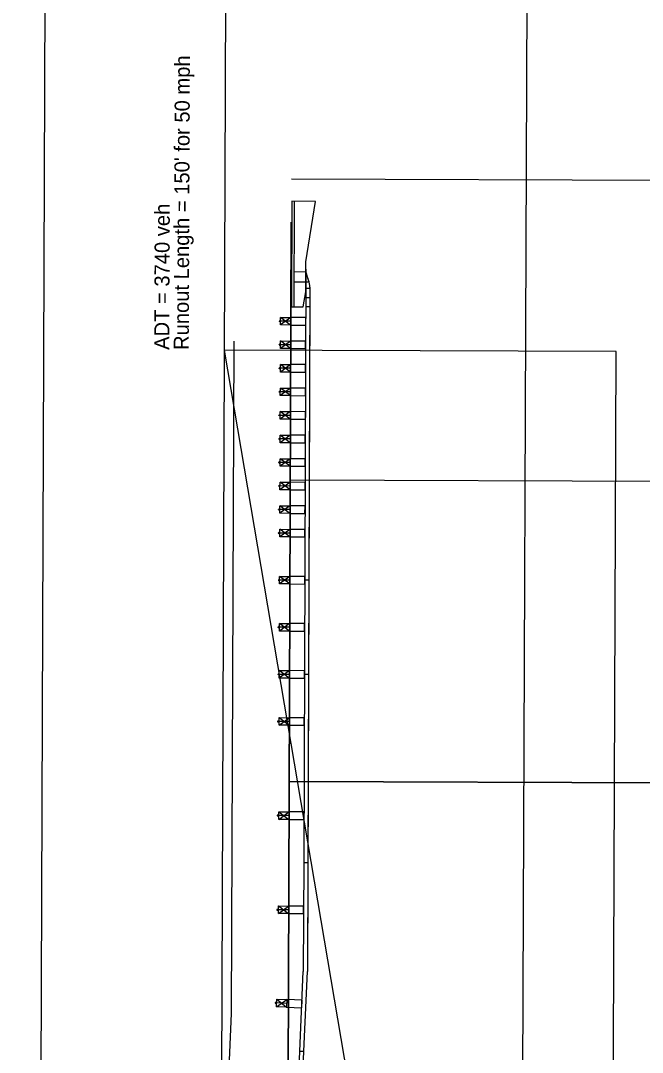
# Model space of a CAD drawing. Extents: x 15359458 to 15360238, y 8797399 to 8799222.
# Drawn here: x 15359893 to 15359934.3, y 8798014.5 to 8798083 of the extents above; entities that cross this region are included whole.
import ezdxf

# ---------------------------------------------------------------- set-up
doc = ezdxf.new("R2010")
doc.units = 0
for name, color, linetype in [('_CIVIL_CONSTRUCTION', 7, 'Continuous'), ('Alignment', 7, 'Continuous'), ('CorridorGraphics', 7, 'Continuous'), ('MeshTop', 7, 'Continuous'), ('PhoTerrainTriangle', 7, 'Continuous'), ('PhoTerrainVoid', 7, 'Continuous')]:
    doc.layers.add(name, color=color, linetype=linetype)

msp = doc.modelspace()

# ---------------------------------------------------------------- linework, layer by layer
at = {"layer": '_CIVIL_CONSTRUCTION'}
for p, q in [((15359911.001, 8798071.023), (15359910.975, 8798064.023)), ((15359912.584, 8798071.017), (15359911.001, 8798071.023)), ((15359911.168, 8798071.022), (15359911.141, 8798064.022)), ((15359911.944, 8798067.018), (15359912.584, 8798071.013)), ((15359912.584, 8798071.013), (15359912.584, 8798071.017)), ((15359911.937, 8798065.019), (15359911.944, 8798067.018)), ((15359911.15, 8798066.356), (15359911.968, 8798066.352)), ((15359911.942, 8798066.519), (15359911.793, 8798027.124)), ((15359911.942, 8798066.519), (15359911.968, 8798066.519)), ((15359911.967, 8798066.269), (15359911.968, 8798066.519)), ((15359911.148, 8798065.689), (15359912.15, 8798065.685)), ((15359912.117, 8798065.785), (15359912.062, 8798065.928)), ((15359911.766, 8798064.02), (15359911.937, 8798065.019)), ((15359912.208, 8798065.227), (15359911.937, 8798065.228)), ((15359912.209, 8798065.323), (15359912.064, 8798027.123)), ((15359912.208, 8798065.227), (15359912.111, 8798039.623)), ((15359910.975, 8798064.023), (15359911.766, 8798064.02)), ((15359912.204, 8798064.018), (15359911.933, 8798064.019)), ((15359912.206, 8798064.622), (15359911.935, 8798064.623)), ((15359910.262, 8798062.817), (15359910.264, 8798063.317)), ((15359910.931, 8798063.315), (15359910.262, 8798062.817)), ((15359910.929, 8798062.815), (15359910.264, 8798063.317)), ((15359910.931, 8798063.314), (15359910.929, 8798062.815)), ((15359911.93, 8798063.311), (15359910.931, 8798063.314)), ((15359911.928, 8798062.811), (15359911.93, 8798063.311)), ((15359910.209, 8798063.077), (15359910.18, 8798063.078)), ((15359910.18, 8798063.058), (15359910.18, 8798063.078)), ((15359910.209, 8798063.057), (15359910.18, 8798063.058)), ((15359910.247, 8798063.107), (15359910.209, 8798063.107)), ((15359910.209, 8798063.027), (15359910.209, 8798063.107)), ((15359910.247, 8798063.091), (15359910.209, 8798063.091)), ((15359910.246, 8798063.043), (15359910.209, 8798063.043)), ((15359910.246, 8798063.027), (15359910.209, 8798063.027)), ((15359910.246, 8798062.987), (15359910.247, 8798063.147)), ((15359910.263, 8798062.987), (15359910.246, 8798062.987)), ((15359910.263, 8798063.147), (15359910.247, 8798063.147)), ((15359910.93, 8798063.065), (15359910.263, 8798063.067)), ((15359910.929, 8798062.815), (15359911.928, 8798062.811)), ((15359910.203, 8798061.515), (15359910.174, 8798061.515)), ((15359910.174, 8798061.495), (15359910.174, 8798061.515)), ((15359910.203, 8798061.495), (15359910.174, 8798061.495)), ((15359910.241, 8798061.545), (15359910.203, 8798061.545)), ((15359910.203, 8798061.465), (15359910.203, 8798061.545)), ((15359910.241, 8798061.529), (15359910.203, 8798061.529)), ((15359910.241, 8798061.481), (15359910.203, 8798061.481)), ((15359910.24, 8798061.465), (15359910.203, 8798061.465)), ((15359910.24, 8798061.425), (15359910.241, 8798061.585)), ((15359910.257, 8798061.425), (15359910.24, 8798061.425)), ((15359910.257, 8798061.585), (15359910.241, 8798061.585)), ((15359910.256, 8798061.255), (15359910.258, 8798061.755)), ((15359910.925, 8798061.752), (15359910.256, 8798061.255)), ((15359910.924, 8798061.502), (15359910.257, 8798061.505)), ((15359910.923, 8798061.252), (15359910.258, 8798061.755)), ((15359910.925, 8798061.752), (15359910.923, 8798061.252)), ((15359910.923, 8798061.252), (15359911.922, 8798061.248)), ((15359911.924, 8798061.748), (15359910.925, 8798061.752)), ((15359911.922, 8798061.248), (15359911.924, 8798061.748)), ((15359910.197, 8798059.952), (15359910.168, 8798059.953)), ((15359910.168, 8798059.933), (15359910.168, 8798059.953)), ((15359910.197, 8798059.932), (15359910.168, 8798059.933)), ((15359910.235, 8798059.982), (15359910.197, 8798059.982)), ((15359910.197, 8798059.902), (15359910.197, 8798059.982)), ((15359910.235, 8798059.966), (15359910.197, 8798059.966)), ((15359910.235, 8798059.918), (15359910.197, 8798059.918)), ((15359910.235, 8798059.902), (15359910.197, 8798059.902)), ((15359910.234, 8798059.862), (15359910.235, 8798060.022)), ((15359910.251, 8798059.862), (15359910.234, 8798059.862)), ((15359910.252, 8798060.022), (15359910.235, 8798060.022)), ((15359910.25, 8798059.692), (15359910.252, 8798060.192)), ((15359910.919, 8798060.19), (15359910.25, 8798059.692)), ((15359910.918, 8798059.94), (15359910.251, 8798059.942)), ((15359910.917, 8798059.69), (15359910.252, 8798060.192)), ((15359910.919, 8798060.189), (15359910.917, 8798059.69)), ((15359911.918, 8798060.186), (15359910.919, 8798060.189)), ((15359911.916, 8798059.686), (15359911.918, 8798060.186)), ((15359910.917, 8798059.69), (15359911.916, 8798059.686)), ((15359910.244, 8798058.13), (15359910.246, 8798058.63)), ((15359910.913, 8798058.627), (15359910.244, 8798058.13)), ((15359910.911, 8798058.127), (15359910.246, 8798058.63)), ((15359910.913, 8798058.627), (15359910.911, 8798058.127)), ((15359911.912, 8798058.623), (15359910.913, 8798058.627)), ((15359911.91, 8798058.123), (15359911.912, 8798058.623)), ((15359910.191, 8798058.39), (15359910.162, 8798058.39)), ((15359910.162, 8798058.37), (15359910.162, 8798058.39)), ((15359910.191, 8798058.37), (15359910.162, 8798058.37)), ((15359910.191, 8798058.34), (15359910.192, 8798058.42)), ((15359910.229, 8798058.404), (15359910.191, 8798058.404)), ((15359910.229, 8798058.356), (15359910.191, 8798058.356)), ((15359910.229, 8798058.34), (15359910.191, 8798058.34)), ((15359910.229, 8798058.42), (15359910.192, 8798058.42)), ((15359910.228, 8798058.3), (15359910.229, 8798058.46)), ((15359910.245, 8798058.3), (15359910.228, 8798058.3)), ((15359910.246, 8798058.46), (15359910.229, 8798058.46)), ((15359910.912, 8798058.377), (15359910.245, 8798058.38)), ((15359910.911, 8798058.127), (15359911.91, 8798058.123)), ((15359910.186, 8798056.827), (15359910.156, 8798056.828)), ((15359910.156, 8798056.808), (15359910.156, 8798056.828)), ((15359910.185, 8798056.807), (15359910.156, 8798056.808)), ((15359910.185, 8798056.777), (15359910.186, 8798056.857)), ((15359910.223, 8798056.793), (15359910.185, 8798056.793)), ((15359910.223, 8798056.777), (15359910.185, 8798056.777)), ((15359910.223, 8798056.857), (15359910.186, 8798056.857)), ((15359910.223, 8798056.841), (15359910.186, 8798056.841)), ((15359910.24, 8798056.897), (15359910.223, 8798056.897)), ((15359910.223, 8798056.737), (15359910.223, 8798056.897)), ((15359910.239, 8798056.737), (15359910.223, 8798056.737)), ((15359910.238, 8798056.567), (15359910.24, 8798057.067)), ((15359910.907, 8798057.065), (15359910.238, 8798056.567)), ((15359910.906, 8798056.815), (15359910.239, 8798056.817)), ((15359910.905, 8798056.565), (15359910.24, 8798057.067)), ((15359910.907, 8798057.064), (15359910.905, 8798056.565)), ((15359910.905, 8798056.565), (15359911.905, 8798056.561)), ((15359911.906, 8798057.061), (15359910.907, 8798057.064)), ((15359911.905, 8798056.561), (15359911.906, 8798057.061)), ((15359910.18, 8798055.265), (15359910.15, 8798055.265)), ((15359910.15, 8798055.245), (15359910.15, 8798055.265)), ((15359910.18, 8798055.245), (15359910.15, 8798055.245)), ((15359910.179, 8798055.215), (15359910.18, 8798055.295)), ((15359910.217, 8798055.231), (15359910.179, 8798055.231)), ((15359910.217, 8798055.215), (15359910.179, 8798055.215)), ((15359910.217, 8798055.295), (15359910.18, 8798055.295)), ((15359910.217, 8798055.279), (15359910.18, 8798055.279)), ((15359910.234, 8798055.335), (15359910.217, 8798055.335)), ((15359910.217, 8798055.175), (15359910.217, 8798055.335)), ((15359910.233, 8798055.175), (15359910.217, 8798055.175)), ((15359910.233, 8798055.005), (15359910.234, 8798055.505)), ((15359910.901, 8798055.502), (15359910.233, 8798055.005)), ((15359910.899, 8798055.002), (15359910.234, 8798055.505)), ((15359910.9, 8798055.252), (15359910.234, 8798055.255)), ((15359910.901, 8798055.502), (15359910.899, 8798055.002)), ((15359911.901, 8798055.498), (15359910.901, 8798055.502)), ((15359911.899, 8798054.998), (15359911.901, 8798055.498)), ((15359910.899, 8798055.002), (15359911.899, 8798054.998)), ((15359910.174, 8798053.702), (15359910.144, 8798053.703)), ((15359910.144, 8798053.683), (15359910.144, 8798053.703)), ((15359910.174, 8798053.682), (15359910.144, 8798053.683)), ((15359910.211, 8798053.732), (15359910.174, 8798053.732)), ((15359910.174, 8798053.652), (15359910.174, 8798053.732)), ((15359910.211, 8798053.716), (15359910.174, 8798053.716)), ((15359910.228, 8798053.772), (15359910.211, 8798053.772)), ((15359910.211, 8798053.612), (15359910.211, 8798053.772)), ((15359910.227, 8798053.442), (15359910.229, 8798053.942)), ((15359910.895, 8798053.94), (15359910.227, 8798053.442)), ((15359910.894, 8798053.69), (15359910.228, 8798053.692)), ((15359910.893, 8798053.44), (15359910.229, 8798053.942)), ((15359910.895, 8798053.94), (15359910.893, 8798053.44)), ((15359911.895, 8798053.936), (15359910.895, 8798053.94)), ((15359911.893, 8798053.436), (15359911.895, 8798053.936)), ((15359910.211, 8798053.668), (15359910.174, 8798053.668)), ((15359910.211, 8798053.652), (15359910.174, 8798053.652)), ((15359910.227, 8798053.612), (15359910.211, 8798053.612)), ((15359910.893, 8798053.44), (15359911.893, 8798053.436)), ((15359910.221, 8798051.88), (15359910.223, 8798052.38)), ((15359910.889, 8798052.377), (15359910.221, 8798051.88)), ((15359910.887, 8798051.877), (15359910.223, 8798052.38)), ((15359910.889, 8798052.377), (15359910.887, 8798051.877)), ((15359910.889, 8798052.377), (15359910.887, 8798051.877)), ((15359911.889, 8798052.373), (15359910.889, 8798052.377)), ((15359911.889, 8798052.373), (15359910.889, 8798052.377)), ((15359911.887, 8798051.873), (15359911.889, 8798052.373)), ((15359911.887, 8798051.873), (15359911.889, 8798052.373)), ((15359910.168, 8798052.14), (15359910.138, 8798052.14)), ((15359910.138, 8798052.12), (15359910.138, 8798052.14)), ((15359910.168, 8798052.12), (15359910.138, 8798052.12)), ((15359910.205, 8798052.17), (15359910.168, 8798052.17)), ((15359910.168, 8798052.09), (15359910.168, 8798052.17)), ((15359910.205, 8798052.154), (15359910.168, 8798052.154)), ((15359910.205, 8798052.106), (15359910.168, 8798052.106)), ((15359910.205, 8798052.09), (15359910.168, 8798052.09)), ((15359910.222, 8798052.21), (15359910.205, 8798052.21)), ((15359910.205, 8798052.05), (15359910.205, 8798052.21)), ((15359910.221, 8798052.05), (15359910.205, 8798052.05)), ((15359910.888, 8798052.127), (15359910.222, 8798052.13)), ((15359910.887, 8798051.877), (15359911.887, 8798051.873)), ((15359910.887, 8798051.877), (15359911.887, 8798051.873)), ((15359910.162, 8798050.578), (15359910.132, 8798050.578)), ((15359910.132, 8798050.558), (15359910.132, 8798050.578)), ((15359910.162, 8798050.558), (15359910.132, 8798050.558)), ((15359910.199, 8798050.607), (15359910.162, 8798050.608)), ((15359910.162, 8798050.528), (15359910.162, 8798050.608)), ((15359910.199, 8798050.591), (15359910.162, 8798050.592)), ((15359910.199, 8798050.543), (15359910.162, 8798050.544)), ((15359910.199, 8798050.527), (15359910.162, 8798050.528)), ((15359910.199, 8798050.487), (15359910.2, 8798050.647)), ((15359910.216, 8798050.487), (15359910.199, 8798050.487)), ((15359910.216, 8798050.647), (15359910.2, 8798050.647)), ((15359910.215, 8798050.317), (15359910.217, 8798050.817)), ((15359910.883, 8798050.815), (15359910.215, 8798050.317)), ((15359910.882, 8798050.565), (15359910.216, 8798050.567)), ((15359910.881, 8798050.315), (15359910.217, 8798050.817)), ((15359910.883, 8798050.815), (15359910.881, 8798050.315)), ((15359910.881, 8798050.315), (15359911.881, 8798050.311)), ((15359911.883, 8798050.811), (15359910.883, 8798050.815)), ((15359911.881, 8798050.311), (15359911.883, 8798050.811)), ((15359910.126, 8798048.995), (15359910.127, 8798049.015)), ((15359910.156, 8798048.995), (15359910.126, 8798048.995)), ((15359910.156, 8798049.015), (15359910.127, 8798049.015)), ((15359910.194, 8798049.045), (15359910.156, 8798049.045)), ((15359910.156, 8798048.965), (15359910.156, 8798049.045)), ((15359910.193, 8798049.029), (15359910.156, 8798049.029)), ((15359910.193, 8798048.981), (15359910.156, 8798048.981)), ((15359910.193, 8798048.965), (15359910.156, 8798048.965)), ((15359910.193, 8798048.925), (15359910.194, 8798049.085)), ((15359910.21, 8798048.925), (15359910.193, 8798048.925)), ((15359910.21, 8798049.085), (15359910.194, 8798049.085)), ((15359910.209, 8798048.755), (15359910.211, 8798049.255)), ((15359910.877, 8798049.252), (15359910.209, 8798048.755)), ((15359910.877, 8798049.002), (15359910.21, 8798049.005)), ((15359910.876, 8798048.752), (15359910.211, 8798049.255)), ((15359910.877, 8798049.252), (15359910.876, 8798048.752)), ((15359911.877, 8798049.248), (15359910.877, 8798049.252)), ((15359911.875, 8798048.749), (15359911.877, 8798049.248)), ((15359910.876, 8798048.752), (15359911.875, 8798048.749)), ((15359910.144, 8798045.89), (15359910.115, 8798045.89)), ((15359910.115, 8798045.87), (15359910.115, 8798045.89)), ((15359910.144, 8798045.87), (15359910.115, 8798045.87)), ((15359910.182, 8798045.92), (15359910.144, 8798045.92)), ((15359910.144, 8798045.84), (15359910.144, 8798045.92)), ((15359910.182, 8798045.904), (15359910.144, 8798045.904)), ((15359910.181, 8798045.856), (15359910.144, 8798045.856)), ((15359910.181, 8798045.84), (15359910.144, 8798045.84)), ((15359910.181, 8798045.8), (15359910.182, 8798045.96)), ((15359910.198, 8798045.8), (15359910.181, 8798045.8)), ((15359910.198, 8798045.96), (15359910.182, 8798045.96)), ((15359910.197, 8798045.63), (15359910.199, 8798046.13)), ((15359910.866, 8798046.127), (15359910.197, 8798045.63)), ((15359910.865, 8798045.877), (15359910.198, 8798045.88)), ((15359910.864, 8798045.627), (15359910.199, 8798046.13)), ((15359910.866, 8798046.127), (15359910.864, 8798045.627)), ((15359910.864, 8798045.627), (15359911.863, 8798045.624)), ((15359911.865, 8798046.123), (15359910.866, 8798046.127)), ((15359911.863, 8798045.624), (15359911.865, 8798046.123)), ((15359912.135, 8798045.873), (15359911.864, 8798045.874)), ((15359910.132, 8798042.765), (15359910.103, 8798042.765)), ((15359910.103, 8798042.745), (15359910.103, 8798042.765)), ((15359910.132, 8798042.745), (15359910.103, 8798042.745)), ((15359910.17, 8798042.795), (15359910.132, 8798042.795)), ((15359910.132, 8798042.715), (15359910.132, 8798042.795)), ((15359910.17, 8798042.779), (15359910.132, 8798042.779)), ((15359910.17, 8798042.731), (15359910.132, 8798042.731)), ((15359910.169, 8798042.675), (15359910.17, 8798042.835)), ((15359910.187, 8798042.835), (15359910.17, 8798042.835)), ((15359910.185, 8798042.505), (15359910.187, 8798043.005)), ((15359910.854, 8798043.002), (15359910.185, 8798042.505)), ((15359910.853, 8798042.752), (15359910.186, 8798042.755)), ((15359910.852, 8798042.502), (15359910.187, 8798043.005)), ((15359910.854, 8798043.002), (15359910.852, 8798042.502)), ((15359911.853, 8798042.998), (15359910.854, 8798043.002)), ((15359911.851, 8798042.499), (15359911.853, 8798042.998)), ((15359910.17, 8798042.715), (15359910.132, 8798042.715)), ((15359910.186, 8798042.675), (15359910.169, 8798042.675)), ((15359910.852, 8798042.502), (15359911.851, 8798042.499)), ((15359910.121, 8798039.64), (15359910.091, 8798039.64)), ((15359910.091, 8798039.62), (15359910.091, 8798039.64)), ((15359910.12, 8798039.62), (15359910.091, 8798039.62)), ((15359910.12, 8798039.59), (15359910.121, 8798039.67)), ((15359910.158, 8798039.606), (15359910.12, 8798039.606)), ((15359910.158, 8798039.59), (15359910.12, 8798039.59)), ((15359910.158, 8798039.67), (15359910.121, 8798039.67)), ((15359910.158, 8798039.654), (15359910.121, 8798039.654)), ((15359910.175, 8798039.71), (15359910.158, 8798039.71)), ((15359910.158, 8798039.55), (15359910.158, 8798039.71)), ((15359910.174, 8798039.55), (15359910.158, 8798039.55)), ((15359910.174, 8798039.38), (15359910.175, 8798039.88)), ((15359910.842, 8798039.877), (15359910.174, 8798039.38)), ((15359910.841, 8798039.627), (15359910.174, 8798039.63)), ((15359910.84, 8798039.377), (15359910.175, 8798039.88)), ((15359910.842, 8798039.877), (15359910.84, 8798039.377)), ((15359910.84, 8798039.377), (15359911.84, 8798039.374)), ((15359911.842, 8798039.873), (15359910.842, 8798039.877)), ((15359911.84, 8798039.374), (15359911.842, 8798039.873)), ((15359912.111, 8798039.623), (15359911.841, 8798039.624)), ((15359910.16, 8798036.255), (15359910.829, 8798036.752)), ((15359910.162, 8798036.755), (15359910.827, 8798036.252)), ((15359910.829, 8798036.752), (15359910.827, 8798036.252)), ((15359911.83, 8798036.749), (15359910.829, 8798036.752)), ((15359911.828, 8798036.248), (15359911.83, 8798036.749)), ((15359910.064, 8798036.505), (15359910.057, 8798036.505)), ((15359910.828, 8798036.502), (15359910.161, 8798036.505)), ((15359910.827, 8798036.252), (15359911.828, 8798036.248)), ((15359910.137, 8798030.005), (15359910.805, 8798030.502)), ((15359910.139, 8798030.505), (15359910.803, 8798030.002)), ((15359910.805, 8798030.502), (15359910.803, 8798030.002)), ((15359911.806, 8798030.499), (15359910.805, 8798030.502)), ((15359911.804, 8798029.998), (15359911.806, 8798030.499)), ((15359910.04, 8798030.255), (15359910.033, 8798030.255)), ((15359910.804, 8798030.252), (15359910.138, 8798030.255)), ((15359910.803, 8798030.002), (15359911.804, 8798029.998)), ((15359911.793, 8798027.124), (15359911.766, 8798019.9)), ((15359912.064, 8798027.123), (15359911.793, 8798027.124)), ((15359912.064, 8798027.123), (15359911.793, 8798027.124)), ((15359912.064, 8798027.123), (15359912.037, 8798019.897)), ((15359910.113, 8798023.755), (15359910.782, 8798024.252)), ((15359910.115, 8798024.255), (15359910.78, 8798023.752)), ((15359910.782, 8798024.252), (15359910.78, 8798023.752)), ((15359911.782, 8798024.249), (15359910.782, 8798024.252)), ((15359911.781, 8798023.748), (15359911.782, 8798024.249)), ((15359910.017, 8798024.005), (15359910.01, 8798024.005)), ((15359910.781, 8798024.002), (15359910.114, 8798024.005)), ((15359910.78, 8798023.752), (15359911.781, 8798023.748)), ((15359911.535, 8798014.625), (15359911.766, 8798019.9)), ((15359911.805, 8798014.613), (15359912.037, 8798019.897)), ((15359909.909, 8798017.826), (15359909.902, 8798017.827)), ((15359909.995, 8798017.572), (15359910.683, 8798018.043)), ((15359910.672, 8798017.793), (15359910.006, 8798017.822)), ((15359910.017, 8798018.072), (15359910.661, 8798017.543)), ((15359910.683, 8798018.043), (15359910.661, 8798017.543)), ((15359910.661, 8798017.543), (15359911.661, 8798017.499)), ((15359911.683, 8798017.999), (15359910.683, 8798018.043)), ((15359911.661, 8798017.499), (15359911.683, 8798017.999)), ((15359911.535, 8798014.625), (15359911.805, 8798014.613))]:
    msp.add_line(p, q, dxfattribs=at)
for points in [[(15359910.931, 8798063.315), (15359910.929, 8798062.815), (15359910.262, 8798062.817), (15359910.264, 8798063.317)], [(15359910.925, 8798061.752), (15359910.923, 8798061.252), (15359910.256, 8798061.255), (15359910.258, 8798061.755)], [(15359910.919, 8798060.19), (15359910.917, 8798059.69), (15359910.25, 8798059.692), (15359910.252, 8798060.192)], [(15359910.913, 8798058.627), (15359910.911, 8798058.127), (15359910.244, 8798058.13), (15359910.246, 8798058.63)], [(15359910.907, 8798057.065), (15359910.905, 8798056.565), (15359910.238, 8798056.567), (15359910.24, 8798057.067)], [(15359910.901, 8798055.502), (15359910.899, 8798055.002), (15359910.233, 8798055.005), (15359910.234, 8798055.505)], [(15359910.895, 8798053.94), (15359910.893, 8798053.44), (15359910.227, 8798053.442), (15359910.229, 8798053.942)], [(15359910.889, 8798052.377), (15359910.887, 8798051.877), (15359910.221, 8798051.88), (15359910.223, 8798052.38)], [(15359910.883, 8798050.815), (15359910.881, 8798050.315), (15359910.215, 8798050.317), (15359910.217, 8798050.817)], [(15359910.877, 8798049.252), (15359910.876, 8798048.752), (15359910.209, 8798048.755), (15359910.211, 8798049.255)], [(15359910.866, 8798046.127), (15359910.864, 8798045.627), (15359910.197, 8798045.63), (15359910.199, 8798046.13)], [(15359910.854, 8798043.002), (15359910.852, 8798042.502), (15359910.185, 8798042.505), (15359910.187, 8798043.005)], [(15359910.842, 8798039.877), (15359910.84, 8798039.377), (15359910.174, 8798039.38), (15359910.175, 8798039.88)], [(15359910.829, 8798036.752), (15359910.827, 8798036.252), (15359910.16, 8798036.255), (15359910.162, 8798036.755)], [(15359910.805, 8798030.502), (15359910.803, 8798030.002), (15359910.137, 8798030.005), (15359910.139, 8798030.505)], [(15359910.782, 8798024.252), (15359910.78, 8798023.752), (15359910.113, 8798023.755), (15359910.115, 8798024.255)], [(15359910.683, 8798018.043), (15359910.661, 8798017.543), (15359909.995, 8798017.572), (15359910.017, 8798018.072)]]:
    msp.add_lwpolyline(points, close=True, dxfattribs=at)
for points in [[(15359910.118, 8798036.525), (15359910.064, 8798036.525), (15359910.064, 8798036.486), (15359910.118, 8798036.486)], [(15359910.161, 8798036.538), (15359910.118, 8798036.538), (15359910.118, 8798036.472), (15359910.161, 8798036.472)], [(15359910.095, 8798030.275), (15359910.04, 8798030.275), (15359910.04, 8798030.236), (15359910.095, 8798030.236)], [(15359910.138, 8798030.288), (15359910.095, 8798030.288), (15359910.094, 8798030.222), (15359910.138, 8798030.222)], [(15359910.071, 8798024.025), (15359910.017, 8798024.025), (15359910.017, 8798023.986), (15359910.071, 8798023.986)], [(15359910.114, 8798024.038), (15359910.071, 8798024.039), (15359910.071, 8798023.972), (15359910.114, 8798023.972)], [(15359909.964, 8798017.843), (15359909.91, 8798017.846), (15359909.908, 8798017.807), (15359909.962, 8798017.804)], [(15359910.007, 8798017.855), (15359909.964, 8798017.857), (15359909.961, 8798017.791), (15359910.004, 8798017.789)]]:
    msp.add_lwpolyline(points, dxfattribs=at)
for centre, major_axis, start_param, end_param in [((15359913.291, 8798066.476), (-0.005, -1.379), 4.866664, 5.124351), ((15359910.714, 8798065.249), (0.006, 1.542), 4.763936, 5.071137)]:
    msp.add_ellipse(centre, major_axis=major_axis, ratio=0.97085, start_param=start_param, end_param=end_param, dxfattribs=at)
at = {"layer": 'Alignment'}
for p, q in [((15359898.874, 8799211.577), (15359893.015, 8797661.588)), ((15359910.874, 8799211.531), (15359905.014, 8797661.542))]:
    msp.add_line(p, q, dxfattribs=at)
msp.add_lwpolyline([(15359906.525, 8798061.15), (15359931.958, 8797911.052), (15359932.525, 8798061.051)], close=True, dxfattribs=at)
at = {"layer": 'CorridorGraphics'}
for p, q in [((15359909.733, 8797973.464), (15359911.535, 8798014.625)), ((15359910.003, 8797973.452), (15359911.805, 8798014.613)), ((15359911.535, 8798014.625), (15359911.805, 8798014.613))]:
    msp.add_line(p, q, dxfattribs=at)
at = {"layer": 'MeshTop'}
for p, q in [((15359912.206, 8798064.622), (15359912.037, 8798019.897)), ((15359907.004, 8798017.126), (15359907.173, 8798061.751)), ((15359904.692, 8797964.321), (15359907.004, 8798017.126))]:
    msp.add_line(p, q, dxfattribs=at)
at = {"layer": 'PhoTerrainTriangle'}
msp.add_line((15359925.969, 8797914.04), (15359928.192, 8798502.036), dxfattribs=at)
at = {"layer": 'PhoTerrainVoid'}
for p, q in [((15359910.985, 8798072.516), (15359954.151, 8798072.353)), ((15359910.974, 8798069.633), (15359910.71, 8797999.633)), ((15359910.974, 8798069.633), (15359910.71, 8797999.633)), ((15359910.71, 8797999.633), (15359910.974, 8798069.633)), ((15359954.097, 8798052.36), (15359910.932, 8798052.523)), ((15359954.097, 8798052.36), (15359910.932, 8798052.523)), ((15359910.856, 8798032.523), (15359954.022, 8798032.36)), ((15359954.022, 8798032.36), (15359910.856, 8798032.523))]:
    msp.add_line(p, q, dxfattribs=at)

# ---------------------------------------------------------------- texts
at = {"layer": 'Alignment'}
for s, p in [("Runout Length = 150' for 50 mph", (15359904.17, 8798061.158)), ('ADT = 3740 veh', (15359902.876, 8798061.163))]:
    msp.add_text(s, height=1, rotation=89.7834, dxfattribs=at).set_placement(p)

doc.saveas('drawing.dxf')
